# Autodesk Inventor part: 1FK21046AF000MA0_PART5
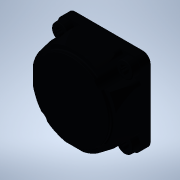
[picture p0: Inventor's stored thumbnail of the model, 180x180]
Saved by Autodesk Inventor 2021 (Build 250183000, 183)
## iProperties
Created: 2025-04
Part Number: 1FK21046AF000MA0_PART5
Material: Generic
Catalog Web Link: www.3dfindit.com
Description: -Servo synchronous motor
Document SubType Name: Modeling
Designer: psAdmin
Mass: 3.92604 g
Surface Area: 17.9521 cm^2
Volume: 3.92604 cm^3
Density: 1 g/cm^3
Appearance: PSOLRGB-48-56-69
Category: PARTsolutions
Title: 1FK21046AF000MA0_PART5
Author: Cadenas PARTsolutions
Comments: Servo synchronous motor
Sending System: PARTsolutions
Preprocessor: ST-DEVELOPER v19.3
PSOL_IDENT_0: {$CADENAS_DATA/23d-libs/siemens_ag/_cat_/1c/1f/1fk21046af000ma0.prj},213 {VTYP=3D},{NB=1FK21046AF000
PSOL_IDENT_1: MA0_PART5},{LINA=1FK21046AF000MA0_PART5},{NN=1FK21046AF000MA0_PART5},{NOPRJ=TRUE},{DATE=19.08.2025 1
PSOL_IDENT_2: 4:00:28},{GEOMDATE=30.07.2025 02:02:08},{VERSION=},{LINEID=10},{WBVAR=},{WBNUMERIC=}  {NB=1FK21046AF
PSOL_IDENT_3: 000MA0_PART5},{LINA=1FK21046AF000MA0_PART5},{KT=DUMMY},{PREVIEW=../../../_pool_/cb/72/p_d211_xx_0043
PSOL_IDENT_4: 4j.png},{DESCSHORT=SIMOTICS S-1FK2 HD, SINAMICS S210 3AC 400V-480V, 3.2 Nm, 3000 rpm},{DESCLONG=SIMO
PSOL_IDENT_5: TICS S-1FK2 HD servo motor M0=3.2 Nm; PN = 1 kW at nN=3000 rpm (380-480 V); PN = 0.5 kW at nN=1500 r
PSOL_IDENT_6: pm (200-240 V); degree of protection IP64; cylindrical shaft D19x40mm; absolute encoder 22-bit + 12-
PSOL_IDENT_7: bit multiturn (encoder AM22DQC); with OCC interface; plug size M17, rotatable; SIMOTICS S-1FK2 servo
PSOL_IDENT_8: motorfor a wide range of uses in industrial environments. SIMOTICS S‑1FK2 servomotors are compact sy
PSOL_IDENT_9: nchronous motors with a high dynamic performance that set themselves apart as a result of their high
PSOL_IDENT_10: power density, degree of protection and overload capability. The motors are available in two varian
PSOL_IDENT_11: ts: as High Dynamic variant (highest dynamic performance as a result of the low intrinsic moment of
PSOL_IDENT_12: inertia for applications demanding a high dynamic performance with low moved masses) - and as Compac
PSOL_IDENT_13: t variant (precise and stable closed-loop control for medium up to large moved masses as a result of
PSOL_IDENT_14: a medium intrinsic moment of inertia). SIMOTICSS‑1FK2 servomotors fully exploit their strengths in
PSOL_IDENT_15: a system with the SINAMICSS210 frequency converter and simple connection using the one cable connect
PSOL_IDENT_16: ion (OCC). Advantages include the short control and positioning times, fast and precise correction o
PSOL_IDENT_17: f disturbing quantities as well as stable control with a high dynamic performance. The servo motors
PSOL_IDENT_18: can be configured to address a wide range of requirements. For example with and without holding brak
PSOL_IDENT_19: e, IP64 or IP65 degree of protection, singleturn or multiturn absolute encoders - to name just a few
PSOL_IDENT_20: . Further, the servomotors are available in different shaft heights extending from 20 to 100. A shaf
PSOL_IDENT_21: t sealing ring is available to achieve an IP65 degree of protection and for subsequent mounting at t
PSOL_IDENT_22: he motor or as spare part. SIMOTICS - the optimum motor for each and every motion control applicatio
PSOL_IDENT_23: n.},{INTNO=195125049666},{SUPPLIERALTNO=1FK2104-6AF00-0MA0},{MANUID=1FK21046AF000MA0},{MANUNAME=Siem
PSOL_IDENT_24: ens},{MANUTYPEDESC=Synchronous motor 1FK2-HD 3.2 NM},{AAU732=SIMOTICS},{AAO057=S-1FK2},{AAU734=SIMOT
PSOL_IDENT_25: ICS S-1FK2 HD servo motor M0=3.2 Nm; PN = 1 kW at nN=3000 rpm (380-480 V); PN = 0.5 kW at nN=1500 rp
PSOL_IDENT_26: m (200-240 V); degree of protection IP64; cylindrical shaft D19x40mm; absolute encoder 22-bit + 12-b
PSOL_IDENT_27: it multiturn (encoder AM22DQC); with OCC interface; plug size M17, rotatable;},{AAW338=Synchronous m
PSOL_IDENT_28: otor 1FK2-HD 3.2 NM},{AAO742=SIMOTICS},{AAO663=4042948694374},{NOCUPEROU=1},{PRICEQUANTITY=1},{QUANT
PSOL_IDENT_29: ITYMIN=1},{QUANTITYINT=1},{CTN=85015220},{COO=DE},{AAO676=1FK2104-6AF00-0MA0},{AAO677=Siemens AG},{O
PSOL_IDENT_30: RDERUNIT=C62},{CONTENTUNIT=C62}
NB: 1FK21046AF000MA0_PART5
NT: Servo synchronous motor
NBSYN: $MANUID._PART5
LINA: 1FK21046AF000MA0_PART5
CATALOG: SIEMENS
PREVIEW: ../../../_pool_/cb/72/p_d211_xx_00434j.png
DESCSHORT: SIMOTICS S-1FK2 HD, SINAMICS S210 3AC 400V-480V, 3.2 Nm, 3000 rpm
DESCLONG: SIMOTICS S-1FK2 HD servo motor M0=3.2 Nm; PN = 1 kW at nN=3000 rpm (380-480 V); PN = 0.5 kW at nN=1500 rpm (200-240 V); degree of protection IP64; cylindrical s
INTNO: 195125049666
SUPPLIERALTNO: 1FK2104-6AF00-0MA0
MANUID: 1FK21046AF000MA0
MANUNAME: Siemens
MANUTYPEDESC: Synchronous motor 1FK2-HD 3.2 NM
AAU732: SIMOTICS
AAO057: S-1FK2
AAU734: SIMOTICS S-1FK2 HD servo motor M0=3.2 Nm; PN = 1 kW at nN=3000 rpm (380-480 V); PN = 0.5 kW at nN=1500 rpm (200-240 V); degree of protection IP64; cylindrical s
AAW338: Synchronous motor 1FK2-HD 3.2 NM
AAO742: SIMOTICS
AAO663: 4042948694374.0
NOCUPEROU: 1
PRICEQUANTITY: 1
QUANTITYMIN: 1
QUANTITYINT: 1
CTN: 85015220
COO: DE
ARTICLENO: 1FK21046AF000MA0_PART5
BOMINFO: 1FK21046AF000MA0_PART5
CREATOR: CADENAS GmbH
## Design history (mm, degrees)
feature "2025_04_17_15_39_11_0362"
body "Solid1"
